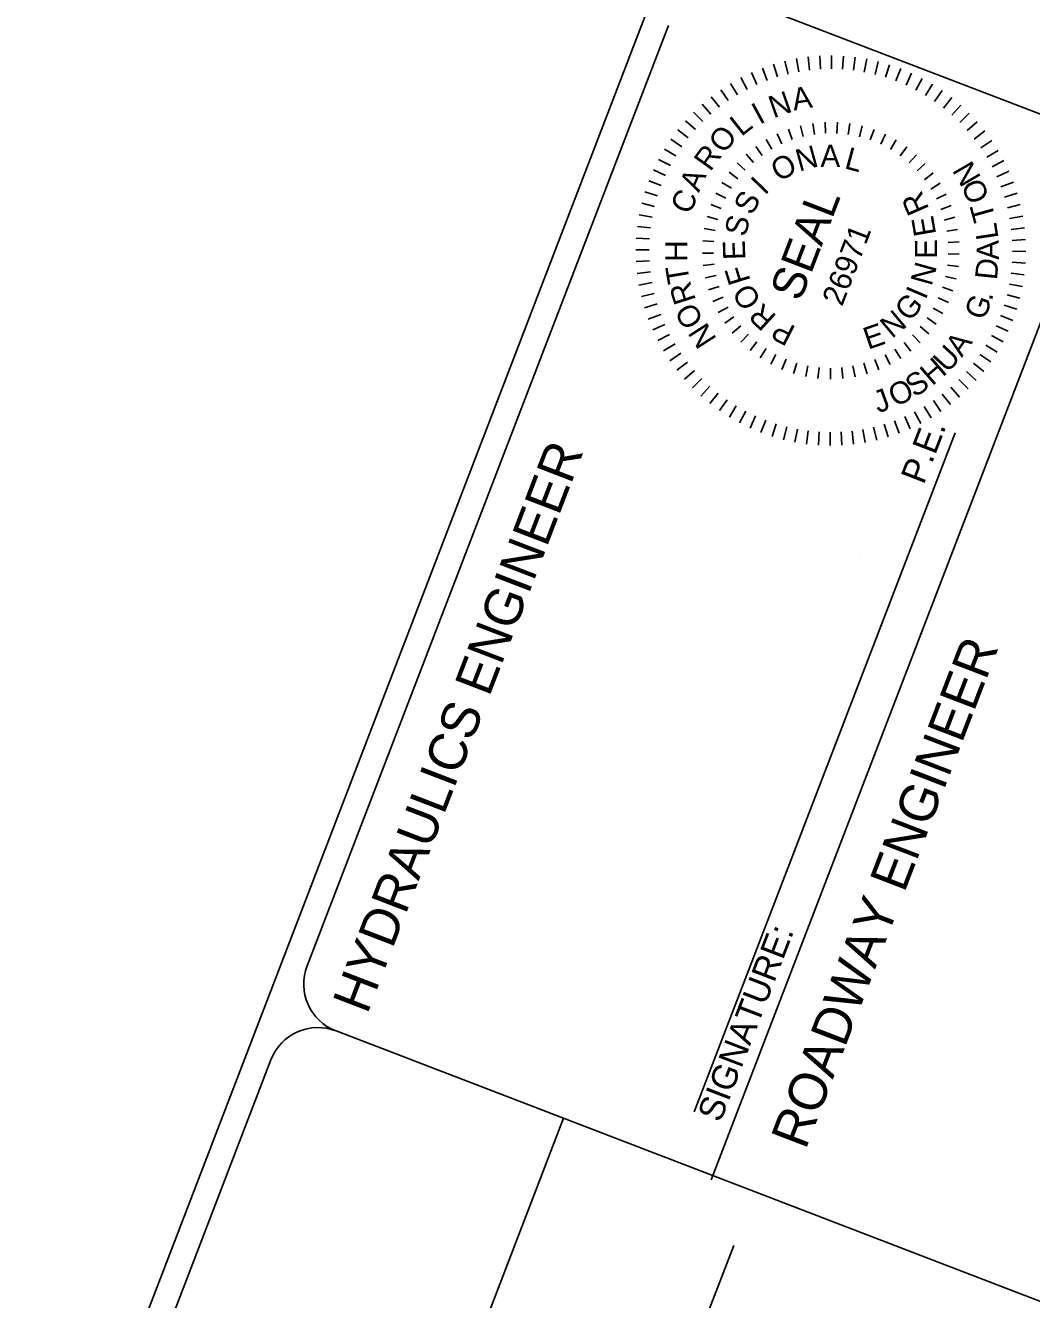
# Model space of a CAD drawing. Extents: x 1015221 to 1064345, y 619216 to 647967.
# Drawn here: x 1025084 to 1026680, y 641845 to 643866 of the extents above; entities that cross this region are included whole.
import ezdxf

# ---------------------------------------------------------------- set-up
doc = ezdxf.new("R2010")
doc.units = 0
for name, color, linetype in [('Scratch_Level_0', 7, 'Continuous'), ('Sheet Professional Seal CELL', 7, 'Continuous'), ('Sheet Title CELL', 7, 'Continuous')]:
    doc.layers.add(name, color=color, linetype=linetype)

msp = doc.modelspace()

# ---------------------------------------------------------------- linework, layer by layer
at = {"layer": 'Scratch_Level_0'}
for p, q in [((1026595.2, 643066.4), (1026595.2, 643066.4)), ((1026407.4, 643024), (1026407.4, 643024))]:
    msp.add_line(p, q, dxfattribs=at)
at = {"layer": 'Sheet Professional Seal CELL'}
for p, q in [((1026270.5, 643804.6), (1026276.7, 643784.4)), ((1026288.5, 643809.5), (1026293.5, 643789)), ((1026306.8, 643813.4), (1026310.5, 643792.6)), ((1026325.3, 643816.1), (1026327.7, 643795.2)), ((1026343.9, 643817.7), (1026345.1, 643796.7)), ((1026362.6, 643818.2), (1026362.5, 643797.1)), ((1026381.2, 643817.6), (1026379.8, 643796.5)), ((1026399.8, 643815.8), (1026397.2, 643794.9)), ((1026418.3, 643812.9), (1026414.4, 643792.2)), ((1026436.5, 643808.9), (1026431.4, 643788.5)), ((1026454.5, 643803.8), (1026448.1, 643783.8)), ((1026218.7, 643783.3), (1026228.4, 643764.6)), ((1026235.5, 643791.4), (1026244.1, 643772.2)), ((1026252.8, 643798.5), (1026260.2, 643778.8)), ((1026472.2, 643797.7), (1026464.6, 643778)), ((1026489.4, 643790.5), (1026480.7, 643771.3)), ((1026506.2, 643782.2), (1026496.3, 643763.6)), ((1026186.6, 643764.1), (1026198.5, 643746.8)), ((1026202.4, 643774.2), (1026213.2, 643756.2)), ((1026522.4, 643773), (1026511.4, 643755)), ((1026538, 643762.8), (1026526, 643745.5)), ((1026157.1, 643741.2), (1026171.1, 643725.4)), ((1026171.6, 643753.1), (1026184.5, 643736.5)), ((1026553.1, 643751.6), (1026540, 643735.1)), ((1026567.4, 643739.6), (1026553.3, 643723.9)), ((1026143.5, 643728.5), (1026158.3, 643713.5)), ((1026580.9, 643726.7), (1026565.9, 643711.9)), ((1026118.6, 643700.6), (1026135.2, 643687.6)), ((1026130.6, 643714.9), (1026146.4, 643700.9)), ((1026294.4, 643701.5), (1026300.2, 643684.9)), ((1026313.3, 643707), (1026317.5, 643690)), ((1026332.7, 643710.7), (1026335.2, 643693.3)), ((1026352.3, 643712.6), (1026353.1, 643695)), ((1026372, 643712.5), (1026371, 643694.9)), ((1026391.6, 643710.5), (1026389, 643693.1)), ((1026410.9, 643706.6), (1026406.6, 643689.6)), ((1026429.8, 643701), (1026423.9, 643684.4)), ((1026593.7, 643713.1), (1026577.8, 643699.2)), ((1026605.6, 643698.7), (1026588.9, 643685.8)), ((1026107.5, 643685.6), (1026124.8, 643673.6)), ((1026258.7, 643685), (1026267.6, 643669.8)), ((1026276.2, 643694.1), (1026283.5, 643678.1)), ((1026448, 643693.4), (1026440.5, 643677.6)), ((1026455.9, 643669.4), (1026464.8, 643684.6)), ((1026616.6, 643683.6), (1026599.2, 643671.7)), ((1026097.3, 643670), (1026115.3, 643659)), ((1026226.8, 643662), (1026238.4, 643648.9)), ((1026242.2, 643674.3), (1026252.5, 643660)), ((1026481.8, 643673.4), (1026471.5, 643659.2)), ((1026497.1, 643661), (1026485.4, 643647.9)), ((1026626.6, 643667.9), (1026608.6, 643657.1)), ((1026088, 643653.7), (1026106.7, 643643.9)), ((1026212.6, 643648.3), (1026225.4, 643636.3)), ((1026511.1, 643647.1), (1026498.2, 643635.3)), ((1026635.8, 643651.6), (1026617.1, 643641.9)), ((1026072.6, 643619.7), (1026092.3, 643612.2)), ((1026079.8, 643637), (1026099, 643628.2)), ((1026188.6, 643617.1), (1026203.5, 643607.8)), ((1026199.8, 643633.3), (1026213.8, 643622.6)), ((1026523.8, 643632.1), (1026509.8, 643621.4)), ((1026643.9, 643634.7), (1026624.6, 643626.2)), ((1026651, 643617.5), (1026631.2, 643610.1)), ((1026066.4, 643602.1), (1026086.5, 643595.7)), ((1026179, 643600), (1026194.7, 643592.1)), ((1026535, 643615.8), (1026520, 643606.6)), ((1026544.4, 643598.5), (1026528.7, 643590.8)), ((1026657, 643599.8), (1026636.9, 643593.6)), ((1026061.3, 643584.1), (1026081.8, 643579)), ((1026171, 643581.9), (1026187.4, 643575.7)), ((1026187.4, 643575.7), (1026171, 643581.9)), ((1026552.2, 643580.5), (1026535.8, 643574.3)), ((1026661.9, 643581.8), (1026641.5, 643576.8)), ((1026057.3, 643565.9), (1026078, 643562)), ((1026164.9, 643563.2), (1026181.8, 643558.5)), ((1026558.2, 643561.7), (1026541.3, 643557.2)), ((1026665.8, 643563.5), (1026645, 643559.7)), ((1026054.4, 643547.4), (1026075.3, 643544.8)), ((1026160.5, 643544), (1026177.8, 643541)), ((1026562.4, 643542.5), (1026545.1, 643539.6)), ((1026668.5, 643545), (1026647.6, 643542.5)), ((1026052.7, 643528.8), (1026073.7, 643527.4)), ((1026158.1, 643524.5), (1026175.6, 643523.1)), ((1026564.7, 643522.9), (1026547.2, 643521.7)), ((1026670.1, 643526.4), (1026649.1, 643525.2)), ((1026052, 643510.1), (1026073.1, 643510.1)), ((1026157.5, 643504.8), (1026175.1, 643505.1)), ((1026565.1, 643503.2), (1026547.5, 643503.7)), ((1026670.7, 643507.7), (1026649.5, 643507.8)), ((1026052.6, 643491.5), (1026073.6, 643492.6)), ((1026158.9, 643485.1), (1026176.3, 643487.2)), ((1026563.6, 643483.6), (1026546.2, 643485.7)), ((1026670, 643489), (1026649, 643490.4)), ((1026054.1, 643472.8), (1026075.1, 643475.3)), ((1026056.9, 643454.3), (1026077.6, 643458.1)), ((1026162.1, 643465.7), (1026179.3, 643469.4)), ((1026560.2, 643464.1), (1026543.1, 643468)), ((1026665.4, 643452), (1026644.7, 643455.9)), ((1026668.2, 643470.4), (1026647.3, 643473.1)), ((1026060.7, 643436.1), (1026081.2, 643441)), ((1026167.2, 643446.7), (1026184, 643452)), ((1026174.1, 643428.2), (1026190.3, 643435.2)), ((1026555, 643445.1), (1026538.3, 643450.7)), ((1026661.4, 643433.7), (1026640.9, 643438.9)), ((1026065.7, 643418.1), (1026085.8, 643424.2)), ((1026182.8, 643410.5), (1026198.2, 643419)), ((1026539.1, 643409.2), (1026523.8, 643417.7)), ((1026547.9, 643426.8), (1026531.8, 643433.8)), ((1026656.3, 643415.8), (1026636.2, 643422.1)), ((1026071.7, 643400.4), (1026091.5, 643407.8)), ((1026193.1, 643393.8), (1026207.6, 643403.7)), ((1026514.2, 643402.4), (1026528.6, 643392.3)), ((1026650.1, 643398.1), (1026630.4, 643405.7)), ((1026078.8, 643383.1), (1026098.1, 643391.7)), ((1026086.9, 643366.3), (1026105.6, 643376)), ((1026205, 643378.1), (1026218.5, 643389.3)), ((1026218.4, 643363.6), (1026230.7, 643376.1)), ((1026503.2, 643362.5), (1026490.9, 643375.1)), ((1026516.6, 643376.9), (1026503.2, 643388.3)), ((1026642.9, 643380.9), (1026623.7, 643389.6)), ((1026096, 643349.9), (1026114.1, 643360.8)), ((1026233.1, 643350.5), (1026244.1, 643364.2)), ((1026488.4, 643349.5), (1026477.4, 643363.2)), ((1026625.4, 643347.9), (1026607.4, 643358.8)), ((1026634.6, 643364.1), (1026616, 643374)), ((1026106.1, 643334.2), (1026123.5, 643346.1)), ((1026249, 643338.8), (1026258.6, 643353.5)), ((1026265.9, 643328.8), (1026274.1, 643344.3)), ((1026283.7, 643320.4), (1026290.4, 643336.6)), ((1026437.5, 643319.8), (1026430.9, 643336.1)), ((1026455.4, 643328), (1026447.3, 643343.6)), ((1026472.4, 643338), (1026462.8, 643352.7)), ((1026615.2, 643332.2), (1026597.9, 643344.2)), ((1026117.1, 643319.1), (1026133.8, 643332)), ((1026129, 643304.7), (1026144.9, 643318.6)), ((1026302.3, 643313.8), (1026307.4, 643330.6)), ((1026321.4, 643309), (1026324.8, 643326.2)), ((1026340.9, 643306.1), (1026342.7, 643323.5)), ((1026360.6, 643305.1), (1026360.6, 643322.6)), ((1026380.2, 643306), (1026378.6, 643323.4)), ((1026399.7, 643308.7), (1026396.4, 643326)), ((1026418.9, 643313.3), (1026413.9, 643330.2)), ((1026592.1, 643302.9), (1026576.3, 643317)), ((1026604.1, 643317.2), (1026587.5, 643330.3)), ((1026141.8, 643291.1), (1026156.7, 643305.9)), ((1026155.3, 643278.2), (1026169.4, 643293.9)), ((1026579.2, 643289.4), (1026564.3, 643304.3)), ((1026169.6, 643266.2), (1026182.7, 643282.8)), ((1026551.1, 643264.7), (1026538.2, 643281.3)), ((1026565.6, 643276.6), (1026551.6, 643292.4)), ((1026184.7, 643255), (1026196.7, 643272.4)), ((1026200.3, 643244.8), (1026211.3, 643262.8)), ((1026216.5, 643235.6), (1026226.4, 643254.2)), ((1026520.3, 643243.6), (1026509.5, 643261.7)), ((1026536, 643253.7), (1026524.2, 643271.1)), ((1026233.3, 643227.4), (1026242, 643246.6)), ((1026250.5, 643220.1), (1026258.1, 643239.8)), ((1026268.2, 643214), (1026274.5, 643234.1)), ((1026452.2, 643213.3), (1026446, 643233.4)), ((1026469.9, 643219.3), (1026462.5, 643239)), ((1026487.2, 643226.4), (1026478.6, 643245.6)), ((1026504, 643234.5), (1026494.3, 643253.2)), ((1026286.2, 643208.9), (1026291.3, 643229.3)), ((1026304.4, 643204.9), (1026308.3, 643225.6)), ((1026322.8, 643202), (1026325.5, 643222.9)), ((1026341.5, 643200.2), (1026342.8, 643221.3)), ((1026360.1, 643199.6), (1026360.2, 643220.7)), ((1026378.8, 643200.1), (1026377.6, 643221.2)), ((1026397.4, 643201.7), (1026395, 643222.7)), ((1026415.9, 643204.5), (1026412.2, 643225.2)), ((1026434.2, 643208.3), (1026429.2, 643228.8))]:
    msp.add_line(p, q, dxfattribs=at)
at = {"layer": 'Sheet Title CELL'}
for p, q in [((1022495.1, 634584.7), (1026569.3, 645189)), ((1027402.1, 643453), (1026207.2, 643912)), ((1025530.7, 642374.2), (1026103.9, 643866)), ((1026171.3, 642034.7), (1026804.5, 643682.6)), ((1026144.4, 642142.7), (1026558.3, 643219.9)), ((1026771.6, 641811.7), (1025576.3, 642271)), ((1024655.2, 640096.6), (1025473, 642224.9)), ((1025937, 642132.4), (1025061.8, 639854.7)), ((1025762.2, 640772.2), (1026207.4, 641930.8))]:
    msp.add_line(p, q, dxfattribs=at)
for centre, start, end in [((1025605, 642345.6), 158.983, 248.983), ((1025547.6, 642196.3), 68.983, 158.983)]:
    msp.add_arc(centre, 80, start, end, dxfattribs=at)

# ---------------------------------------------------------------- texts
at = {"layer": 'Sheet Professional Seal CELL'}
for s, height, rotation, p in [('N', 35.1, 19.2913, (1026270.2, 643718.6)), ('A', 35.1, 9.5237, (1026302.7, 643731)), ('I', 35.1, 28.5857, (1026248.4, 643708.1)), ('L', 35.1, 38.1612, (1026219.2, 643689)), ('O', 35.1, 51.2975, (1026191.8, 643661.2)), ('R', 35.1, 54.3543, (1026170.2, 643633.1)), ('O', 35.1, 30.766, (1026279.5, 643617.1)), ('N', 35.1, 15.4698, (1026311.2, 643634)), ('A', 35.1, 0.1735, (1026344.9, 643641.6)), ('L', 35.1, 344.8773, (1026381.4, 643639.8)), ('N', 35.1, 120.3042, (1026600.5, 643624.7)), ('A', 35.1, 66.3636, (1026152.1, 643600.2)), ('I', 35.1, 46.0623, (1026256.6, 643595.6)), ('O', 35.1, 112.8997, (1026613.8, 643593.1)), ('C', 35.1, 66.3636, (1026137.7, 643564.7)), ('S', 35.1, 61.3585, (1026236.2, 643563.5)), ('R', 35.1, 113.5715, (1026517.7, 643574.9)), ('SEAL', 52.7, 69.0066, (1026312.8, 643426.4)), ('T', 35.1, 105.4952, (1026622.9, 643560)), ('S', 35.1, 76.6548, (1026226.3, 643529.7)), ('E', 35.1, 99.8004, (1026528.6, 643534.9)), ('26971', 35.11, 69.0066, (1026379.2, 643419.2)), ('L', 35.1, 98.6879, (1026627.5, 643528.7)), ('H', 35.1, 90.0743, (1026133.7, 643491.3)), ('E', 35.1, 91.951, (1026225.8, 643494.6)), ('E', 35.1, 89.8146, (1026529.7, 643495.9)), ('A', 35.1, 91.2834, (1026628.2, 643494.4)), ('T', 35.1, 99.5062, (1026137.8, 643459.5)), ('F', 35.1, 107.2472, (1026234.3, 643461.2)), ('N', 35.1, 74.4225, (1026521, 643451.5)), ('D', 35.1, 84.1177, (1026624.7, 643461.4)), ('R', 35.1, 107.6672, (1026147.7, 643430.4)), ('O', 35.1, 122.5435, (1026252.3, 643429.3)), ('G', 35.1, 48.698, (1026485.9, 643394.7)), ('I', 35.1, 66.7928, (1026511.4, 643429.7)), ('G', 35.1, 69.5476, (1026605, 643396.9)), ('.', 35.1, 76.7132, (1026616.7, 643428)), ('O', 35.1, 120.7239, (1026160.7, 643398.2)), ('R', 35.1, 137.8397, (1026276.8, 643405)), ('N', 35.1, 39.9318, (1026458.3, 643368.5)), ('N', 35.1, 122.6834, (1026181.2, 643368.7)), ('P', 35.1, 153.136, (1026307.4, 643387.6)), ('E', 35.1, 19.0767, (1026420.4, 643351.5)), ('U', 35.1, 47.4535, (1026546.2, 643313.7)), ('A', 35.1, 54.7386, (1026569.1, 643338.6)), ('H', 35.1, 40.6461, (1026522.1, 643293.3)), ('S', 35.1, 33.4805, (1026494.3, 643275.1)), ('O', 35.1, 26.076, (1026463.5, 643260.1)), ('J', 35.1, 19.8657, (1026436.3, 643250.6))]:
    msp.add_text(s, height=height, rotation=rotation, dxfattribs=at).set_placement(p)
at = {"layer": 'Sheet Title CELL'}
for s, height, p in [('P.E.', 40, (1026508.7, 643136.4)), (' HYDRAULICS ENGINEER', 60, (1025617.8, 642275.3)), ('ROADWAY ENGINEER', 59.995, (1026321.1, 642081.1)), ('SIGNATURE:', 40, (1026186.1, 642124.3))]:
    msp.add_text(s, height=height, rotation=68.983, dxfattribs=at).set_placement(p)

doc.saveas('drawing.dxf')
